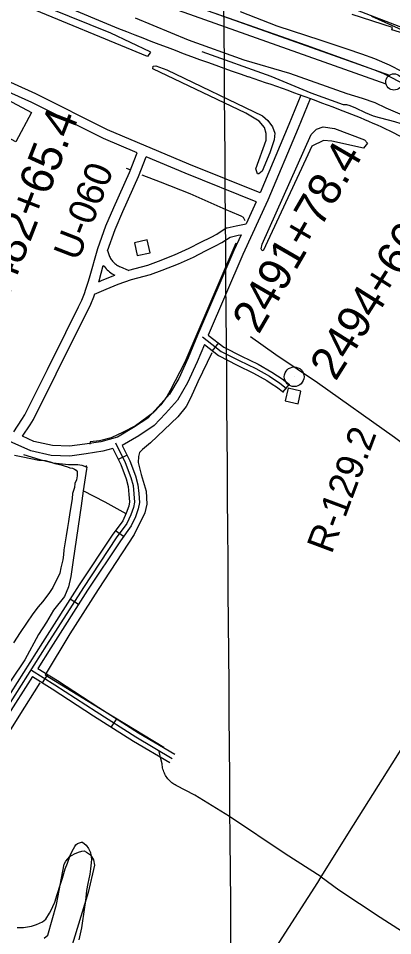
# Model space of a CAD drawing. Extents: x 3535183 to 3573198, y 534952 to 560562.
# Drawn here: x 3554542 to 3555683, y 542262 to 545059 of the extents above; entities that cross this region are included whole.
import ezdxf

# ---------------------------------------------------------------- set-up
doc = ezdxf.new("R2010")
doc.units = 0
for name, color, linetype in [('V-BLDG-OTLN', 7, 'Continuous'), ('V-DTCH-CNTR', 7, 'Continuous'), ('V-FLOD-BASE', 7, 'Continuous'), ('V-GRID-MAJR', 7, 'Continuous'), ('V-LEVE-TOET', 7, 'Continuous'), ('V-RIVR-EDGE', 7, 'Continuous'), ('V-RIVR-RANG-IDEN', 7, 'Continuous'), ('V-ROAD-CNTR', 7, 'Continuous'), ('V-RRAP-RVMT', 7, 'Continuous'), ('V-SITE-VEGE', 7, 'Continuous'), ('V-SURV-IDEN', 7, 'Continuous'), ('V-SURV-LINE', 7, 'Continuous'), ('V-TOPO-MINR', 7, 'Continuous'), ('V-TOPO-SHOR', 7, 'Continuous'), ('V-TOPO-TOWR', 7, 'Continuous')]:
    doc.layers.add(name, color=color, linetype=linetype)

msp = doc.modelspace()

# ---------------------------------------------------------------- linework, layer by layer
at = {"layer": 'V-BLDG-OTLN'}
for points in [[(3554582.5, 544771.7), (3554534.6, 544682.3), (3554445.3, 544730.2), (3554493.2, 544819.6)], [(3554904.7, 544335.9), (3554943.8, 544344.6), (3554935.1, 544383.6), (3554896.1, 544375)], [(3555355.7, 543892.4), (3555394.8, 543883.7), (3555403.5, 543922.8), (3555364.4, 543931.4)]]:
    msp.add_lwpolyline(points, close=True, dxfattribs=at)
at = {"layer": 'V-DTCH-CNTR'}
for points in [[(3554751.1, 541312.2), (3554800.3, 541389.4), (3554913.7, 541572.2), (3555073.4, 541825), (3555190.3, 542006), (3555307.4, 542195), (3555454.9, 542423.8), (3555465.4, 542440.8), (3555563.6, 542598.6), (3555699.2, 542813.3), (3555849.7, 543059.2), (3556006.7, 543306.7), (3556109.3, 543476.3), (3556141.5, 543529.5), (3556269.6, 543730), (3556370.1, 543898.7), (3556466.8, 544060.3), (3556500.2, 544111.7)], [(3556109.3, 543476.3), (3555931.2, 543599.5), (3555688.7, 543781.4), (3555453.9, 543948), (3555327.2, 544033.2), (3555249.2, 544087.8)], [(3555465.4, 542440.8), (3555355.4, 542511.3), (3555185.2, 542625.3), (3555080.5, 542690.4), (3555023.6, 542719.4), (3555020, 542721.4), (3555016.4, 542723.6), (3555013, 542725.9), (3555009.7, 542728.4), (3555006.6, 542731.1), (3555003.5, 542734), (3555000.7, 542737), (3554998, 542740.2), (3554995.4, 542743.5), (3554993.1, 542746.9), (3554990.9, 542750.4), (3554988.9, 542754.1), (3554987.1, 542757.8), (3554985.4, 542761.6), (3554984, 542765.5), (3554982.8, 542769.5), (3554981.8, 542773.5), (3554981, 542777.6), (3554980.4, 542781.7), (3554980, 542785.9), (3554976.7, 542801.2), (3554971.1, 542823.2)], [(3555465.4, 542440.8), (3555518.6, 542402), (3555645.4, 542318.5), (3555821, 542205.3), (3555942.6, 542131.8), (3556018.8, 542256.1), (3556068.2, 542343.1)]]:
    msp.add_lwpolyline(points, dxfattribs=at)
at = {"layer": 'V-FLOD-BASE'}
msp.add_lwpolyline([(3555714.9, 544859.6), (3555682.1, 544876.9), (3555656.2, 544889.6), (3555625.9, 544902.5), (3555555.7, 544927.5), (3555420.5, 544976.5), (3555222.8, 545046), (3555037.3, 545110.9)], dxfattribs=at)
at = {"layer": 'V-GRID-MAJR'}
msp.add_spline([(3555204.2, 540472.4), (3555158.4, 546529.8), (3555112.5, 552590.7), (3555066.7, 558651.5), (3555066.7, 558655)], degree=3, dxfattribs=at)
at = {"layer": 'V-LEVE-TOET'}
for points in [[(3555628.7, 544935.5), (3555588.8, 544950.3), (3555544.6, 544965.1), (3555464.9, 544992.1), (3555331.3, 545035), (3555219.5, 545079.2)], [(3554898.5, 545060.7), (3555059.8, 544993.6), (3555229, 544932.4), (3555368.1, 544892), (3555543.5, 544829.9), (3555590.4, 544815.8), (3555628.6, 544802.8), (3555662.4, 544786.3), (3555704.9, 544768)], [(3555920.3, 544765.4), (3555855.8, 544810.4), (3555795.4, 544846.5), (3555764.4, 544867.2), (3555713.5, 544896.2), (3555673.7, 544916.2), (3555628.7, 544935.5)]]:
    msp.add_lwpolyline(points, dxfattribs=at)
at = {"layer": 'V-RIVR-EDGE'}
msp.add_lwpolyline([(3555618.7, 545066.4), (3555720.6, 545019.9)], dxfattribs=at)
at = {"layer": 'V-ROAD-CNTR'}
for p, q in [((3555266.8, 544499.5), (3555236.3, 544432.8)), ((3555151.7, 544069.4), (3555133.3, 544045.7)), ((3555367.2, 543943.8), (3555348.6, 543920.3)), ((3554873.5, 543727), (3554846.7, 543713.6)), ((3554862.4, 543479.2), (3554838.2, 543496.9)), ((3554724.9, 543271.6), (3554699.6, 543287.7)), ((3554630.6, 543058.6), (3554614.6, 543033.2)), ((3554841.1, 542923.6), (3554825, 542898.3))]:
    msp.add_line(p, q, dxfattribs=at)
for points in [[(3554034.2, 545377.8), (3554275.5, 545272.5), (3554669.5, 545103), (3554847.6, 545028.6)], [(3555279, 544526.9), (3555062, 544614.8), (3554814, 544719.7), (3554595.6, 544829.5), (3554421.9, 544907.2), (3554322.3, 544967.5), (3554290.8, 545001.1), (3554283.9, 545010.8)], [(3554904, 544649), (3554801.4, 544692.5), (3554582.7, 544802.4), (3554407.9, 544880.6), (3554303.2, 544944), (3554296.5, 544951.2)], [(3555403.5, 544825.3), (3555367, 544735.8), (3555279, 544526.9)], [(3555431.3, 544813.9), (3555394.7, 544724.3), (3555302.4, 544505.2), (3555226.2, 544338.8), (3555120.9, 544093.4)], [(3554528, 543798.1), (3554552.8, 543835.7), (3554561.4, 543850.4), (3554630.4, 543988.3), (3554686.8, 544101.5), (3554725.9, 544180), (3554735.7, 544200.2), (3554743.6, 544220.1), (3554748, 544233.5), (3554754.8, 544254.5), (3554759.2, 544267.9), (3554784.5, 544357.8), (3554809, 544426.1), (3554833.1, 544482), (3554880.6, 544589), (3554904, 544649)], [(3554813.8, 544350.7), (3554837, 544415.1), (3554860.6, 544469.9), (3554908.3, 544577.5), (3554931.6, 544637.3)], [(3555266.8, 544499.5), (3555050.5, 544587), (3554931.6, 544637.3)], [(3555175.5, 544420.1), (3555178.1, 544420.7), (3555205.8, 544427), (3555236.3, 544432.8)], [(3554876.7, 544290.8), (3554878.4, 544291.4), (3554936.3, 544306.8), (3554969.7, 544318.9), (3555018.5, 544338.6), (3555062.8, 544358.4), (3555098.8, 544376.7), (3555129.4, 544391.7), (3555146.8, 544401.5), (3555175.5, 544420.1)], [(3555220.9, 544399.3), (3555198.7, 544350.9), (3555088.3, 544093.5), (3555060, 544024), (3555031.3, 543961.3), (3555002.4, 543913.2), (3554968.5, 543874.4), (3554936.6, 543840.5), (3554893.1, 543811.2), (3554844.4, 543782.4), (3554793.3, 543768.3), (3554744.3, 543760.6), (3554697.9, 543754.6), (3554645.8, 543756.4), (3554589.7, 543769.2), (3554555.1, 543784.7)], [(3554774.4, 544217.9), (3554809.4, 544233.4), (3554846.8, 544248.2), (3554887.3, 544262.7), (3554945.2, 544278.1), (3554980.4, 544290.9), (3555030.2, 544311), (3555075.8, 544331.3), (3555112.2, 544349.9), (3555143.3, 544365.1), (3555162.3, 544375.8), (3555187.5, 544392.1)], [(3555187.5, 544392.1), (3555211.9, 544397.6), (3555220.9, 544399.3)], [(3554814.1, 544351.6), (3554814.1, 544351.6), (3554814.7, 544348.3), (3554815.5, 544345.1), (3554816.4, 544341.9), (3554817.5, 544338.7), (3554818.7, 544335.7), (3554820.1, 544332.6), (3554821.7, 544329.7), (3554823.4, 544326.8), (3554825.2, 544324.1), (3554827.1, 544321.4), (3554829.2, 544318.8), (3554831.4, 544316.3), (3554833.8, 544314), (3554836.2, 544311.7), (3554838.8, 544309.6), (3554841.4, 544307.6), (3554844.2, 544305.8), (3554847, 544304.1), (3554850, 544302.5), (3554853, 544301.1), (3554877.3, 544291)], [(3554786.9, 544256.1), (3554787.9, 544259.2), (3554801, 544305.9)], [(3554801.1, 544306.1), (3554803.4, 544303.1), (3554806.4, 544299.3), (3554809.6, 544295.8), (3554813, 544292.3), (3554816.5, 544289.1), (3554820.2, 544286), (3554824.1, 544283.1), (3554828.1, 544280.5), (3554832.2, 544278), (3554835.8, 544276.1)], [(3554786.9, 544256.2), (3554797.8, 544261.1), (3554836.2, 544276.2), (3554836.3, 544276.3)], [(3554555.1, 543784.7), (3554578.3, 543819.8), (3554587.8, 543836.2), (3554657.2, 543974.9), (3554713.7, 544088.1), (3554752.9, 544166.8), (3554763.2, 544188.1), (3554771.8, 544209.9), (3554774.8, 544219.1)], [(3555120.9, 544093.4), (3555168.7, 544056.1), (3555222.1, 544028.9), (3555272.6, 544004.3), (3555315, 543980.5), (3555332.3, 543969.3), (3555346.4, 543960.3), (3555368.7, 543942.6)], [(3555103.1, 544088.2), (3555160.6, 544043.4), (3555215.4, 544015.5), (3555265.7, 543991), (3555307.3, 543967.7), (3555324.1, 543956.7), (3555337.6, 543948), (3555359.4, 543930.8)], [(3555109, 544064.6), (3555087.5, 544012.1), (3555057.9, 543947.3), (3555026.8, 543895.4), (3554990.7, 543854.3), (3554956.1, 543817.5), (3554909.1, 543785.8), (3554859, 543756.2)], [(3555109, 544064.6), (3555152.5, 544030.7), (3555208.8, 544002), (3555258.7, 543977.7), (3555299.5, 543954.8), (3555316, 543944.1), (3555328.9, 543935.8), (3555350.1, 543919.1)], [(3554837.8, 543765.1), (3554868, 543704.4), (3554885, 543659.2), (3554891.7, 543634.2), (3554894.3, 543608.9), (3554896.1, 543583.8), (3554893, 543567.8), (3554884.9, 543545.2), (3554873.1, 543519.2), (3554840.7, 543475), (3554740.4, 543323.7), (3554628, 543147.5), (3554492.5, 542934.5), (3554259.1, 542562.5), (3554118, 542347.1), (3554031.8, 542210.5)], [(3554829.9, 543747.3), (3554799.7, 543739), (3554748.5, 543730.9), (3554699.3, 543724.5), (3554641.9, 543726.5), (3554580.1, 543740.6), (3554513.9, 543770.2)], [(3554829.9, 543747.3), (3554854.3, 543698.4), (3554870.7, 543654.6), (3554876.9, 543631.5), (3554879.3, 543607.6), (3554881, 543584.7), (3554878.5, 543571.8), (3554871, 543550.8), (3554860.1, 543526.8), (3554828.4, 543483.5), (3554727.8, 543331.9), (3554615.4, 543155.6), (3554479.8, 542942.5), (3554246.5, 542570.6), (3554105.4, 542355.2), (3554019.1, 542218.6)], [(3554859, 543756.2), (3554881.8, 543710.4), (3554899.4, 543663.8), (3554906.5, 543636.9), (3554909.2, 543610.2), (3554911.2, 543582.9), (3554907.5, 543563.9), (3554898.8, 543539.5), (3554886.1, 543511.6), (3554853, 543466.4), (3554753, 543315.5), (3554640.7, 543139.4), (3554601, 543077.1)], [(3554580.3, 543072.5), (3554582.3, 543071.2), (3554652.8, 543026.9), (3554779, 542945.4), (3554900.5, 542868), (3555011.3, 542802.5)], [(3554601, 543077.1), (3554660.9, 543039.6), (3554787.1, 542958), (3554908.4, 542880.8), (3555018.9, 542815.4)], [(3554584.9, 543051.8), (3554505.2, 542926.5), (3554271.7, 542554.4), (3554130.7, 542339), (3554044.4, 542202.4), (3553990.6, 542119.6), (3553969.8, 542076.8), (3553962.5, 542046.4), (3553963.8, 542021.1), (3553982.1, 541972.8), (3554024.2, 541935.9), (3554054.7, 541912.8)], [(3554584.9, 543051.8), (3554644.7, 543014.3), (3554770.9, 542932.7), (3554892.7, 542855.3), (3555003.7, 542789.6)]]:
    msp.add_lwpolyline(points, dxfattribs=at)
for centre, radius, start, end in [((3558403, 553951.7), 9605.3, 248.27502, 250.79546), ((3552816.7, 537717.1), 7563.7, 69.06856, 71.28618), ((3554932.8, 543189.2), 1696.8, 62.1413, 69.7957)]:
    msp.add_arc(centre, radius, start, end, dxfattribs=at)
at = {"layer": 'V-RRAP-RVMT'}
msp.add_lwpolyline([(3555820.3, 544981.3), (3555680.1, 545024.4), (3555682.4, 545031.6), (3555559.8, 545070.7)], dxfattribs=at)
at = {"layer": 'V-SITE-VEGE'}
for points in [[(3554935.9, 544943), (3554546.7, 545103.9), (3554475.7, 545134.3), (3554463.5, 545144.2), (3554487, 545147.9), (3554507.5, 545143.3), (3554823, 545015.6), (3554943.1, 544958), (3554944.4, 544956.6)], [(3555266.2, 544600.2), (3555297, 544687.7), (3555297.4, 544708.3), (3555292.2, 544726.3), (3555276.1, 544745.9), (3555235.3, 544770.2), (3554951.6, 544905.5), (3554953.2, 544913.7), (3554961.5, 544915), (3554994.2, 544901.9), (3555286.1, 544762.3), (3555302.3, 544748.2), (3555317.1, 544728.6), (3555323.6, 544709.2), (3555321.8, 544688.5), (3555308.6, 544648.9), (3555285.4, 544592.9), (3555275.6, 544584.8), (3555271.4, 544584.9)], [(3555594, 544663.6), (3555498, 544684.9), (3555471.9, 544686.8), (3555437.1, 544669.6), (3555418.4, 544630.1), (3555288.6, 544350.4), (3555284.5, 544351.9), (3555281.9, 544356.1), (3555284.9, 544371.1), (3555435.1, 544705.5), (3555450.5, 544721.7), (3555471.3, 544728.1), (3555505.7, 544723.3), (3555597.2, 544688.4), (3555606.7, 544678.5)]]:
    msp.add_lwpolyline(points, close=True, dxfattribs=at)
for points in [[(3554530.8, 543726.9), (3554556, 543722.5), (3554604.4, 543712.3), (3554623.8, 543710.7), (3554638.8, 543706.8), (3554652.9, 543702), (3554672.2, 543697.9), (3554681.3, 543695), (3554692.1, 543691.2), (3554698.8, 543688.5), (3554707.2, 543687.3)], [(3554707.2, 543687.3), (3554713, 543684.6), (3554718.7, 543681), (3554721.1, 543677.5), (3554721.7, 543669.9), (3554721.4, 543664), (3554719.3, 543652.3), (3554714.7, 543640.7), (3554713.4, 543628.9), (3554707.6, 543609.8), (3554706.2, 543594.6), (3554701.9, 543569.5), (3554698.7, 543552.8), (3554695.1, 543525.1), (3554691.9, 543506.7), (3554687.5, 543480.7), (3554684.3, 543463.2), (3554680.9, 543438.8), (3554679.5, 543423.7), (3554677.2, 543407.8), (3554672, 543383.6), (3554668, 543366.9), (3554647, 543323.8), (3554634.5, 543304.9), (3554615.9, 543279.5), (3554602.7, 543264.8), (3554585.8, 543243.6), (3554547.4, 543186.9), (3554526.8, 543154.8)], [(3554538.6, 542287.1), (3554558, 542287.2), (3554582.6, 542291.3), (3554597.1, 542295.8), (3554616, 542304.4), (3554625.5, 542312.5), (3554637.2, 542330.6), (3554640.8, 542338), (3554652.8, 542364.5), (3554660.4, 542387), (3554670.9, 542418.6), (3554676.6, 542436.9), (3554684.4, 542465.3), (3554691.8, 542482.7), (3554700.3, 542506), (3554705.9, 542519.3), (3554714, 542533.3), (3554717.6, 542539.1), (3554721.9, 542543.1), (3554734.7, 542546.8), (3554738.1, 542546.7), (3554748.7, 542537.9), (3554755.9, 542527.5), (3554762.2, 542515.5), (3554763.5, 542507), (3554764.8, 542495.1), (3554764.4, 542484.2), (3554762, 542465.7), (3554759.7, 542449.8), (3554753.5, 542420.5), (3554749.4, 542399.6), (3554746.5, 542368.6), (3554743.2, 542348.5), (3554734.9, 542285.6), (3554726.8, 542248.8)]]:
    msp.add_lwpolyline(points, dxfattribs=at)
at = {"layer": 'V-SURV-LINE'}
for points in [[(3554850.9, 545179.3), (3555673.3, 544886.3)], [(3555663.3, 544858.1), (3554840.9, 545151)]]:
    msp.add_lwpolyline(points, dxfattribs=at)
msp.add_circle((3555687.1, 544865.5), 25, dxfattribs=at)
at = {"layer": 'V-TOPO-MINR'}
msp.add_lwpolyline([(3555522.4, 545104.7), (3555987.3, 544926)], dxfattribs=at)
at = {"layer": 'V-TOPO-SHOR'}
for p, q in [((3554870.2, 544602.8), (3554885.3, 544597.3)), ((3554750.4, 543690.5), (3554750.2, 543696.1))]:
    msp.add_line(p, q, dxfattribs=at)
for points in [[(3555101.2, 544958.7), (3555311.6, 544882.6), (3555434, 544831.8), (3555531.8, 544797)], [(3555531.8, 544797), (3555541.9, 544796.1), (3555552.6, 544793.9), (3555569.9, 544786.2), (3555599.7, 544772.1), (3555623.7, 544762.3), (3555641.7, 544757.2), (3555669, 544749.9), (3555688.4, 544744.8), (3555707.7, 544739.1), (3555725, 544734), (3555733.7, 544730.5), (3555743, 544725.6), (3555746.9, 544722.2), (3555748.2, 544712.7)], [(3554918.3, 544582.3), (3554974.6, 544560.5), (3555064.5, 544525.1), (3555174.1, 544475.9), (3555212.7, 544459.7), (3555220.7, 544456.9), (3555227.3, 544453.4), (3555232.7, 544442.9)], [(3555205.2, 544374.2), (3555147.1, 544238.4), (3555049.3, 544010.4), (3555005.3, 543924.1), (3554994.9, 543906.2), (3554976.2, 543880.4), (3554952.9, 543856.1), (3554899.1, 543816.2), (3554861.9, 543796.9), (3554825.3, 543780.2), (3554789.6, 543770.9), (3554761.3, 543768.1), (3554759.6, 543760.6)], [(3555131.9, 544039.7), (3555089, 543951.2), (3555067.2, 543901.4), (3555053.2, 543875.5), (3555028.5, 543844.5), (3554944.4, 543764.4), (3554920.5, 543744.1), (3554910.9, 543735.5), (3554908, 543723.5), (3554907.6, 543704.8), (3554916.2, 543668.4), (3554931.3, 543617.8), (3554933.9, 543578.1), (3554927.9, 543551.4), (3554895.1, 543485.7), (3554785.7, 543317.6), (3554699.1, 543181.9), (3554623.4, 543057)], [(3554557.6, 543729.6), (3554607.3, 543713.5), (3554648, 543704), (3554694.9, 543699), (3554723, 543698.4), (3554735.7, 543696.2), (3554743.7, 543693.3), (3554750.4, 543690.5), (3554749.6, 543684.5), (3554740, 543618.9), (3554733.2, 543572.8), (3554709.1, 543407), (3554702, 543357.5), (3554694.7, 543325.5), (3554682.7, 543296.2), (3554648.9, 543254.7), (3554627.4, 543218.2), (3554603.2, 543180.5), (3554561.4, 543103.5), (3554475.6, 542975.8)], [(3554870.2, 543547.9), (3554807.1, 543583.4), (3554740, 543618.9)], [(3554607.6, 543033), (3554543.8, 542931.5), (3554464.8, 542807.7), (3554359.5, 542643.6), (3554262.5, 542491.3), (3554166.2, 542337.7)], [(3554623.4, 543057), (3554805, 542946.3), (3554985.1, 542836.7)], [(3554621.2, 542254.6), (3554632.1, 542263.8), (3554658.2, 542357.2), (3554682.1, 542480.1), (3554686.3, 542489.4), (3554699.4, 542503.2), (3554713, 542511.6), (3554725.8, 542516.1), (3554735.9, 542519.2), (3554742.6, 542520.4), (3554749.3, 542516.9), (3554761.8, 542508), (3554770.9, 542493), (3554774.6, 542476.8), (3554754.8, 542393.4), (3554692.3, 542186.8)]]:
    msp.add_lwpolyline(points, dxfattribs=at)
at = {"layer": 'V-TOPO-TOWR'}
msp.add_line((3555382.8, 543966.3), (3555382.8, 543966.3), dxfattribs=at)
msp.add_circle((3555382.8, 543966.3), 30, dxfattribs=at)

# ---------------------------------------------------------------- texts
at = {"layer": 'V-RIVR-RANG-IDEN'}
for s, rotation, p in [('U-060', 68.7923, (3554724.3, 544316.1)), ('R-129.2', 69.5386, (3555497, 543423.3))]:
    msp.add_text(s, height=83, rotation=rotation, dxfattribs=at).set_placement(p)
at = {"layer": 'V-SURV-IDEN'}
for s, rotation, p in [('2482+65.4', 68.7522, (3554496.6, 544166)), ('2491+78.4', 59.877, (3555274.8, 544093.2)), ('2494+66.4', 57.8701, (3555509.2, 543950.3))]:
    msp.add_text(s, height=100, rotation=rotation, dxfattribs=at).set_placement(p)

doc.saveas('drawing.dxf')
